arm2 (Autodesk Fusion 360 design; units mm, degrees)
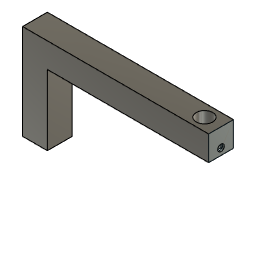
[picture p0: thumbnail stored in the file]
sketch "草图1" plane through (0, 0, 0) normal (0, 0, 1) x axis (1, 0, 0)
  line L1 (-7.5, 7.5) -> (7.5, 7.5)
  line L2 (-7.5, -7.5) -> (-7.5, 7.5)
  line L3 (7.5, -7.5) -> (-7.5, -7.5)
  line L4 (7.5, 7.5) -> (7.5, -7.5)
  line L5 (-7.5, -7.5) -> (7.5, 7.5)
  line L6 (7.5, -7.5) -> (-7.5, 7.5)
  point P6 (0, 0)
  point P1 (0, 0)
  point P4 (-7.5, -7.5)
  point P5 (7.5, -7.5)
  horizontal L1
  perpendicular L1 L2
  parallel L1 L3
  parallel L2 L4
  coincident L5 P6
  coincident L6 P6
  coincident P1 P6
  dimension "d1" distance P4 P5 = 15
  dimension "d2" distance L1 L3 = 15
sketch "草图2" plane through (0, 0, 0) normal (0, 1, 0) x axis (1, 0, 0)
  line L1 (0, -40) -> (0, 0)
  line L2 (87, -50) -> (10, -50)
  line L3 (0, -50) -> (10, -50)
  line L4 (0, -40) -> (0, -50)
  point P1 (0, 0)
  point P2 (0, 0)
  point P3 (0, -50)
  point P7 (0, -50)
  point P4 (87, -50)
  coincident P1 P2
  vertical L1
  perpendicular L1 L2
  coincident P3 L2
  coincident P3 L1
  coincident P3 P7
  dimension "d3" distance P2 P3 = 50
  dimension "d4" distance P3 P4 = 87
sweep "扫掠" sketch "草图1" TwistAngle 0 TaperAngle 0
sketch "草图5" plane through (0, 0, 0) normal (0, 0, -1) x axis (1, 0, 0)
  line L1 (7.5, 7.5) -> (7.5, -7.5)
  line L2 (-7.5, 7.5) -> (7.5, 7.5)
  line L3 (-7.5, -7.5) -> (-7.5, 7.5)
  line L4 (7.5, -7.5) -> (-7.5, -7.5)
  circle C1 centre (0, 0) radius 1.75
  point P1 (0, 0)
  point P10 (0, 0)
  coincident P1 P10
  dimension "d24" diameter C1 = 3.5
extrude "拉伸2" cut sketch "草图5" profile of C1 against normal blind 10
sketch "草图6" plane through (0, 0, 0) normal (0, 0, -1) x axis (1, 0, 0)
  line L1 (7.5, 7.5) -> (7.5, -7.5)
  line L2 (-7.5, 7.5) -> (7.5, 7.5)
  line L3 (-7.5, -7.5) -> (-7.5, 7.5)
  line L4 (7.5, -7.5) -> (-7.5, -7.5)
  line L5 (-6, 4) -> (-3, 4)
  line L6 (-6, -4) -> (-6, 4)
  line L7 (-3, -4) -> (-6, -4)
  line L8 (-3, 4) -> (-3, -4)
  line L9 (-6, -4) -> (-3, 4)
  line L10 (-3, -4) -> (-6, 4)
  circle C1 centre (0, 0) radius 1.75
  point P15 (-4.5, 0)
  point P13 (-6, -4)
  point P14 (-3, -4)
  point P1 (0, 0)
  horizontal L5
  perpendicular L5 L6
  parallel L5 L7
  parallel L6 L8
  coincident L9 P15
  coincident L10 P15
  dimension "d27" distance P13 P14 = 3
  dimension "d28" distance L5 L7 = 8
  dimension "d29" distance P1 P15 = 4.5
extrude "拉伸3" cut sketch "草图6" profile of L5 L6 L7 L8 against normal blind 10
sketch "草图7" plane through (-7.5, 0, 0) normal (-1, 0, 0) x axis (0, -1, 0)
  line L1 (7.5, 0) -> (-7.5, 0)
  line L2 (7.5, 57.5) -> (7.5, 0)
  line L3 (-7.5, 0) -> (-7.5, 57.5)
  line L4 (-7.5, 57.5) -> (7.5, 57.5)
  circle C1 centre (0, 4) radius 2
  point P6 (0, 4)
  dimension "d32" diameter C1 = 4
  dimension "d33" distance L1 P6 = 4
extrude "拉伸4" cut sketch "草图7" profile of C1 against normal blind 7.5
sketch "草图8" plane through (87, 0, 0) normal (1, 0, 0) x axis (0, 1, 0)
  line L1 (7.5, 42.5) -> (-7.5, 42.5)
  line L2 (7.5, 57.5) -> (7.5, 42.5)
  line L3 (-7.5, 57.5) -> (7.5, 57.5)
  line L4 (-7.5, 42.5) -> (-7.5, 57.5)
  line L5 (-7.5, 57.5) -> (7.5, 57.5)
  line L6 (-7.5, 42.5) -> (-7.5, 57.5)
  line L7 (7.5, 42.5) -> (-7.5, 42.5)
  line L8 (7.5, 57.5) -> (7.5, 42.5)
  line L9 (-7.5, 42.5) -> (7.5, 57.5)
  line L10 (7.5, 42.5) -> (-7.5, 57.5)
  point P10 (0, 50)
  point P4 (7.5, 57.5)
  point P6 (7.5, 57.5)
  horizontal L5
  perpendicular L5 L6
  parallel L5 L7
  parallel L6 L8
  coincident L9 P10
  coincident L10 P10
  coincident P4 P6
extrude "拉伸5" add sketch "草图8" profile of L1 L2 L3 L4 L5 L6 L7 L8 along normal blind 10
sketch "草图9" plane through (0, 0, 57.5) normal (0, 0, 1) x axis (-1, 0, 0)
  line L1 (-97, 7.5) -> (7.5, 7.5)
  line L2 (-97, -7.5) -> (-97, 7.5)
  line L3 (7.5, -7.5) -> (-97, -7.5)
  line L4 (7.5, 7.5) -> (7.5, -7.5)
  circle C1 centre (-94.5, -0.04) radius 4
  point P6 (-94.5, -0.04)
  dimension "d59" diameter C1 = 8
  dimension "d60" distance L2 P6 = 2.5
extrude "拉伸7" cut of existing geometry blind -2
extrude "拉伸9" add of existing geometry blind 10
sketch "草图11" plane through (0, 0, 57.5) normal (0, 0, 1) x axis (-1, 0, 0)
  line L1 (7.5, -7.5) -> (-105, -7.5)
  line L2 (7.5, 7.5) -> (7.5, -7.5)
  line L3 (-105, 7.5) -> (7.5, 7.5)
  line L4 (-105, -7.5) -> (-105, 7.5)
  circle C1 centre (-95, 0) radius 5
  dimension "d71" diameter C1 = 10
sketch "草图13" plane through (0, 0, 42.5) normal (0, 0, -1) x axis (1, 0, 0)
  line L1 (7.5, 7.5) -> (105, 7.5)
  line L2 (7.5, -7.5) -> (7.5, 7.5)
  line L3 (105, -7.5) -> (7.5, -7.5)
  line L4 (105, 7.5) -> (105, -7.5)
  line L5 (104, -4) -> (101, -4)
  line L6 (104, 4) -> (104, -4)
  line L7 (101, 4) -> (104, 4)
  line L8 (101, -4) -> (101, 4)
  line L9 (101, 0) -> (101, 0)
  point P10 (101, 0)
  point P6 (101, -4)
  point P7 (104, -4)
  horizontal L5
  vertical L6
  horizontal L7
  vertical L8
  coincident L8 P10
  perpendicular L6 L9
  dimension "d76" distance P6 P7 = 3
  dimension "d77" distance L5 L9 = 4
  dimension "d78" distance L5 L7 = 8
extrude "拉伸10" cut sketch "草图11" profile of C1 against normal blind 27
extrude "拉伸11" cut sketch "草图13" profile of L5 L6 L7 L8 against normal blind 10
sketch "草图14" plane through (105, 0, 0) normal (1, 0, 0) x axis (0, 1, 0)
  line L1 (7.5, 57.5) -> (7.5, 42.5)
  line L2 (-7.5, 57.5) -> (7.5, 57.5)
  line L3 (-7.5, 42.5) -> (-7.5, 57.5)
  line L4 (7.5, 42.5) -> (-7.5, 42.5)
sketch "草图15" plane through (105, 0, 0) normal (1, 0, 0) x axis (0, 1, 0)
  line L1 (7.5, 42.5) -> (-7.5, 42.5)
  circle C1 centre (0, 46.5) radius 2
  point P2 (0, 46.5)
  dimension "d81" diameter C1 = 4
  dimension "d82" distance P2 L1 = 4
extrude "拉伸12" cut sketch "草图15" profile of C1 against normal blind 8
